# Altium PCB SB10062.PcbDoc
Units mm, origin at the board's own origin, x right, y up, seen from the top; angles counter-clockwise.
Board outline 100 x 62 mm, 2 copper layers (Top Layer, Bottom Layer); 0 components, 0 nets, 4 pads, 0 vias.
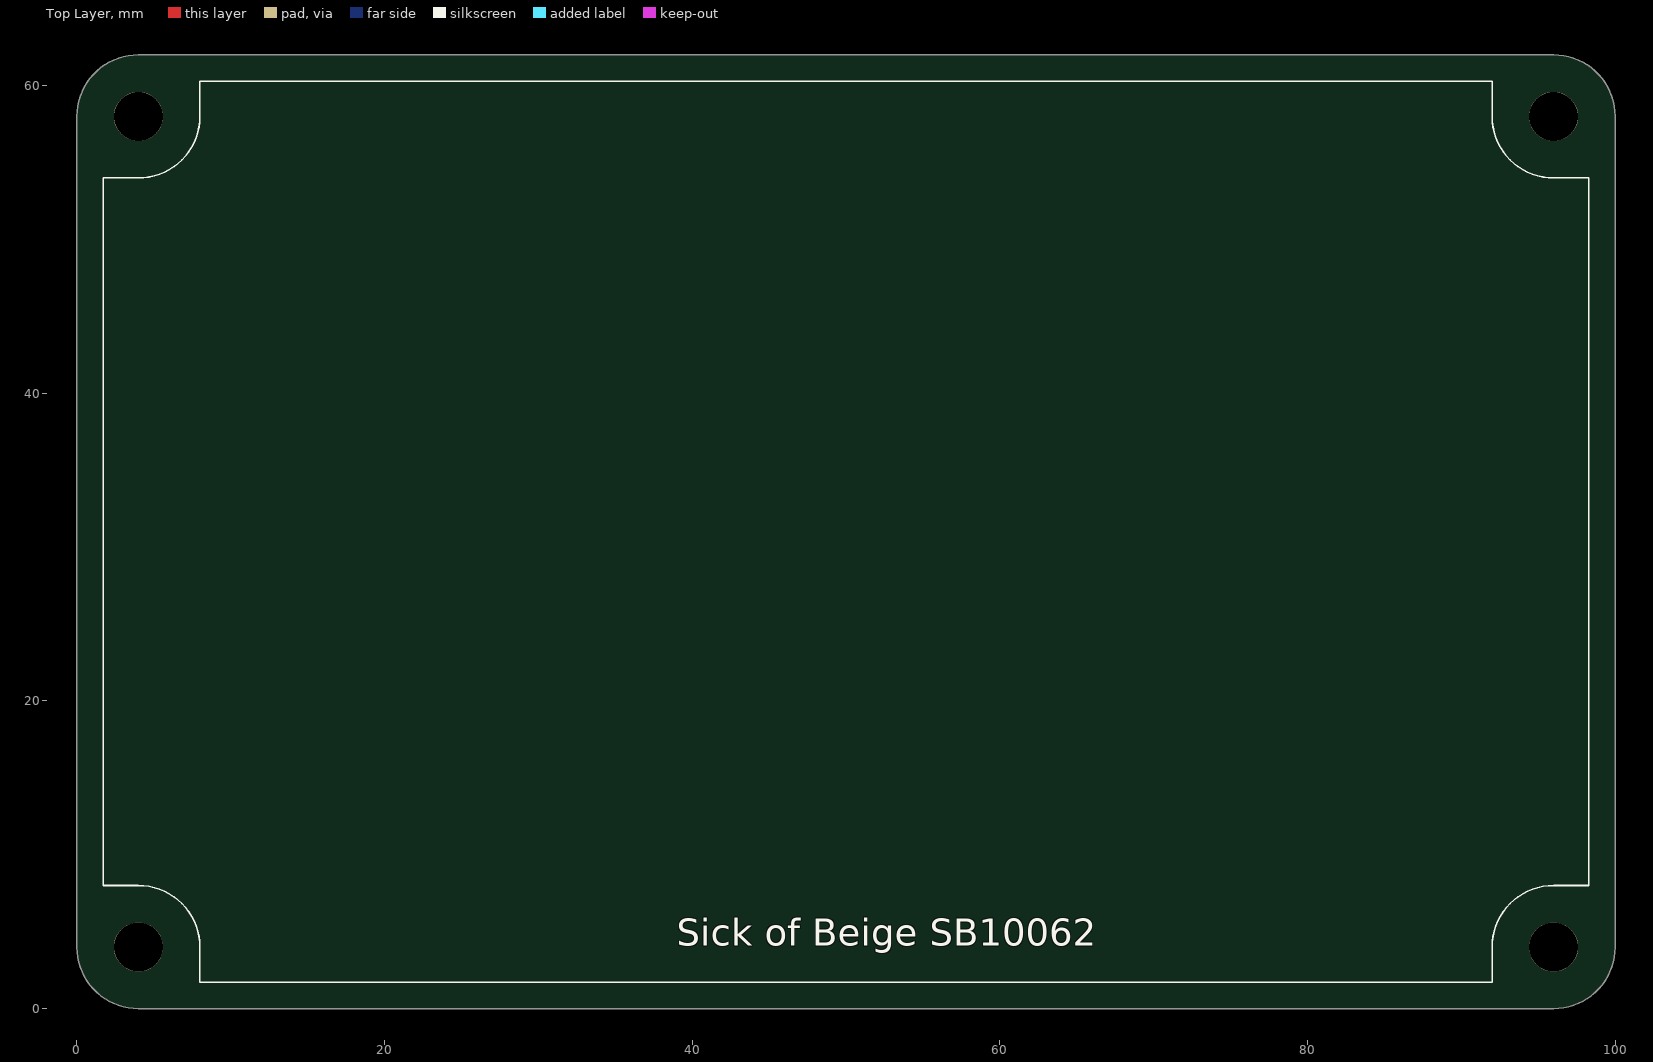
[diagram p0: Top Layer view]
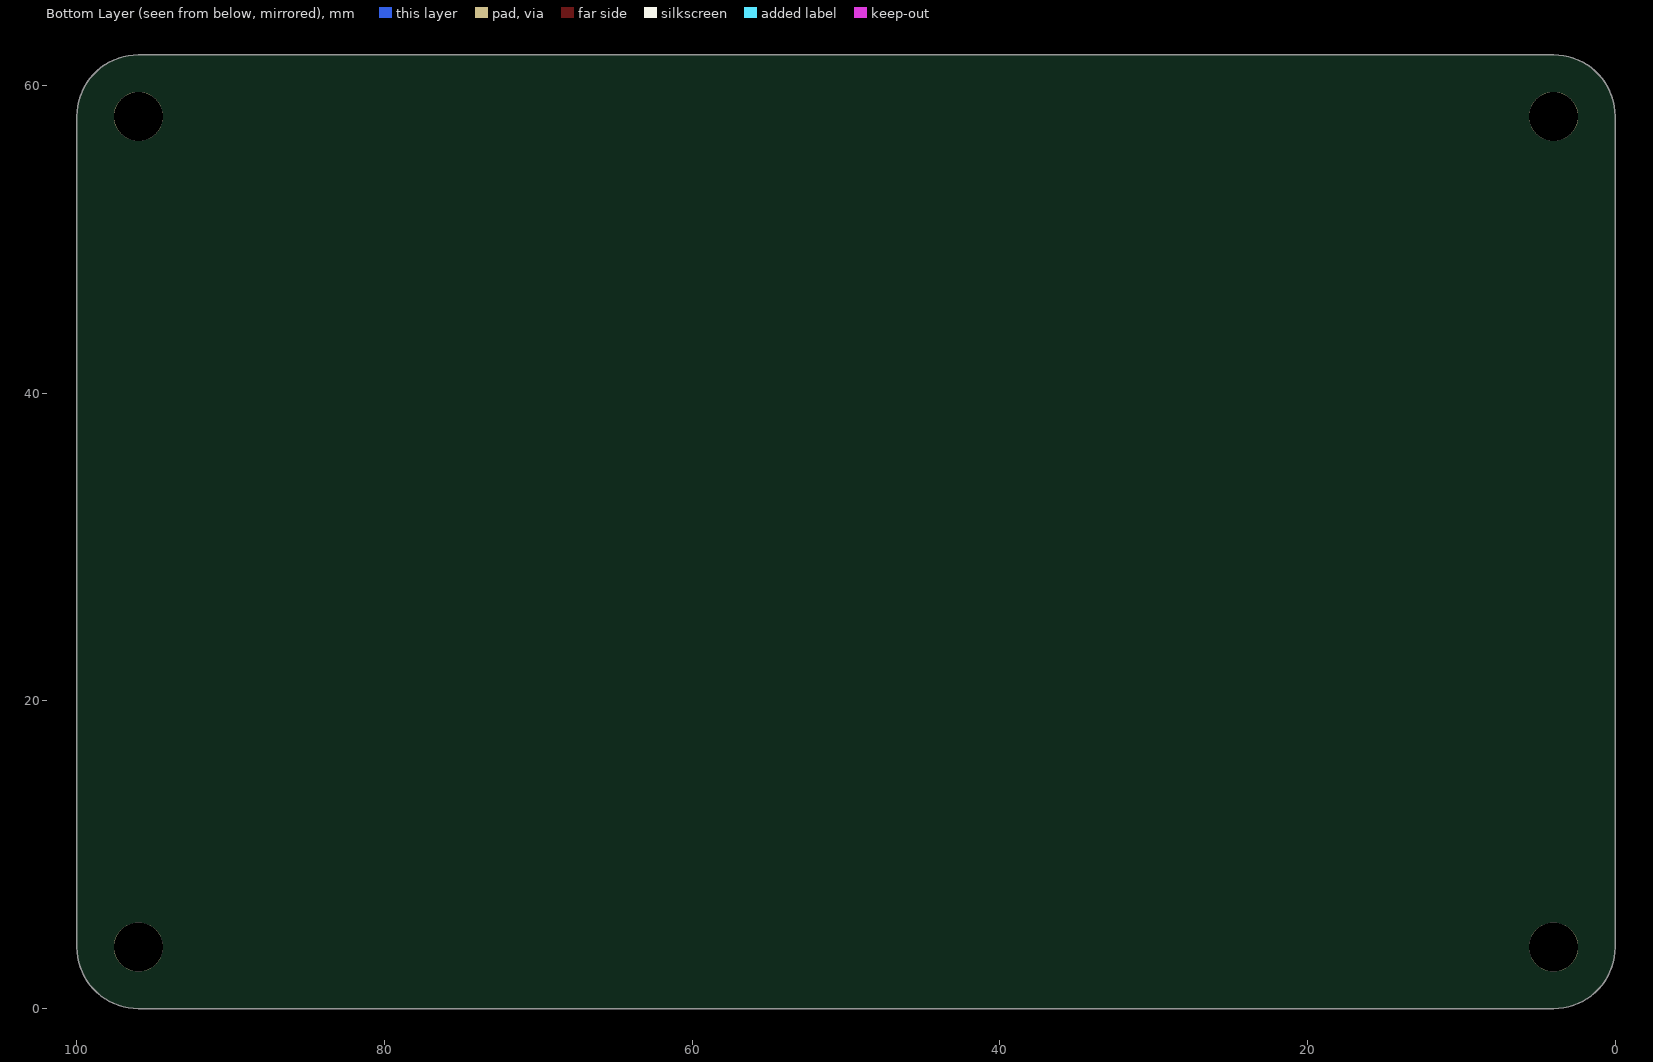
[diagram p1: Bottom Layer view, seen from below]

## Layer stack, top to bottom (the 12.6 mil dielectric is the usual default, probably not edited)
Top Layer: signal copper 0.0356
Dielectric: dielectric 0.32, FR-4, Dk 4.8
Bottom Layer: signal copper 0.0356

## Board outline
4,0 cw(c4,4) 0,4 0,58 cw(c4,58) 4,62 96,62 cw(c96,58) 100,58 100,4 cw(c96,4) 96,0

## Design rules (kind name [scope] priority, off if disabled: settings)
Clearance [All] p1: gap=0.254
PolygonConnect [All] p1: connectstyle=Relief reliefconductorwidth=0.254 reliefentries=4 polygonreliefangle="90 Angle" airgapwidth=0.254
RoutingVias [All] p1: holewidth=0.711 width=1.27 viastyle="Through Hole" minholewidth=0.711 minwidth=1.27 maxholewidth=0.711 maxwidth=1.27
SolderMaskExpansion [All] p1: expansion=0.102
Width [All] p1: maxlimit=0.254 minlimit=0.254 preferedwidth=0.254
28 further rules are at their usual default settings.

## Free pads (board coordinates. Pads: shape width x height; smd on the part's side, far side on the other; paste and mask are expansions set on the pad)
  round 3.2 hole 3.2 unplated: 0(4,4) 1(4,58) 2(96,58) 3(96,4)

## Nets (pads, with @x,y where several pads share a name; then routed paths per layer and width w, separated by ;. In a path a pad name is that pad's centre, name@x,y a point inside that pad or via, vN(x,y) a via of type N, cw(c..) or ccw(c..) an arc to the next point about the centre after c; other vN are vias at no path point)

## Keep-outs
Top Overlay:
  lines w0.102: 92,58 ccw(c96,58) 96,54 98.3,54 98.3,8.5 98.3,8 96,8 ccw(c96,4) 92,4 92,1.7 8,1.7 8,4 ccw(c4,4) 4,8 1.7,8 1.7,54 4,54 ccw(c4,58) 8,58 8,60.3 92,60.3 92,58 ; 92,58 92,58

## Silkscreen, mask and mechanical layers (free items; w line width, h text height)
Top Overlay:
  text "Sick of Beige SB10062" at 39,3.5 h3
Mechanical 1:
  the board outline again, w0.102
Mechanical 4:
  circle w0.102: c96,58 r1.6
  circle w0.102: c4,58 r1.6
  circle w0.102: c4,4 r1.6
  circle w0.102: c96,4 r1.6
  lines w0.102: 0,31 100,31 ; 50,0 50,62

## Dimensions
0,4 to 100,4 on Mechanical 3
96,62 to 96,0 on Mechanical 3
